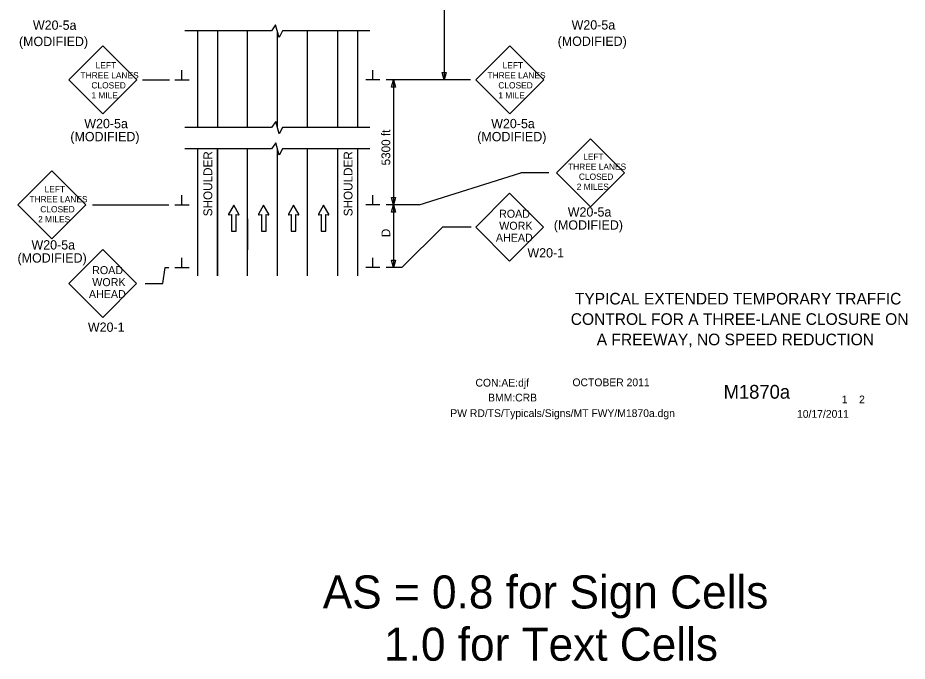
# Model space of a CAD drawing. Extents: x 16724 to 18475, y 7025 to 8210.
# Drawn here: x 16725 to 17436, y 7025 to 7539 of the extents above; entities that cross this region are included whole.
import ezdxf

# ---------------------------------------------------------------- set-up
doc = ezdxf.new("R2010")
doc.units = 0
for name, color, linetype in [('BORDER', 7, 'Continuous'), ('BORDER_SIGNAL_WO', 7, 'Continuous'), ('Level 3', 7, 'Continuous'), ('MT_SCRATCH_LEVEL_E', 7, 'Continuous'), ('PAVT_EDGE_EX', 7, 'Continuous'), ('TRAFFIC_SIGNS_PR', 7, 'Continuous'), ('TYPICAL_TEXT_DIMEN_PR', 7, 'Continuous')]:
    doc.layers.add(name, color=color, linetype=linetype)

msp = doc.modelspace()

# ---------------------------------------------------------------- linework, layer by layer
at = {"layer": 'Level 3'}
msp.add_line((16840.68, 7326.73), (16842.33, 7339.56), dxfattribs=at)
at = {"layer": 'MT_SCRATCH_LEVEL_E'}
for p, q in [((16897.35, 7389.48), (16893.24, 7382.24)), ((16901.49, 7382.24), (16897.35, 7389.48)), ((16921.25, 7389.48), (16917.14, 7382.24)), ((16925.4, 7382.24), (16921.25, 7389.48)), ((16945.16, 7389.48), (16941.05, 7382.24)), ((16949.3, 7382.24), (16945.16, 7389.48)), ((16969.21, 7389.48), (16965.1, 7382.24)), ((16973.36, 7382.24), (16969.21, 7389.48)), ((16893.72, 7381.55), (16895.5, 7381.87)), ((16895.5, 7381.87), (16895.5, 7368.61)), ((16899.24, 7368.61), (16899.24, 7381.87)), ((16899.24, 7381.87), (16901.02, 7381.55)), ((16917.62, 7381.55), (16919.4, 7381.87)), ((16919.4, 7381.87), (16919.4, 7368.61)), ((16923.14, 7368.61), (16923.14, 7381.87)), ((16923.14, 7381.87), (16924.92, 7381.55)), ((16941.53, 7381.55), (16943.3, 7381.87)), ((16943.3, 7381.87), (16943.3, 7368.61)), ((16947.05, 7368.61), (16947.05, 7381.87)), ((16947.05, 7381.87), (16948.82, 7381.55)), ((16965.58, 7381.55), (16967.36, 7381.87)), ((16967.36, 7381.87), (16967.36, 7368.61)), ((16971.1, 7368.61), (16971.1, 7381.87)), ((16971.1, 7381.87), (16972.88, 7381.55)), ((16895.5, 7368.61), (16899.24, 7368.61)), ((16919.4, 7368.61), (16923.14, 7368.61)), ((16943.3, 7368.61), (16947.05, 7368.61)), ((16967.36, 7368.61), (16971.1, 7368.61))]:
    msp.add_line(p, q, dxfattribs=at)
for centre, start, end in [((16893.64, 7382.01), 150.42484, 279.96381), ((16901.09, 7382.01), 260.03619, 29.77312), ((16917.55, 7382.01), 150.42484, 279.96381), ((16924.99, 7382.01), 260.03619, 29.77312), ((16941.45, 7382.01), 150.42484, 279.96381), ((16948.89, 7382.01), 260.03619, 29.77312), ((16965.51, 7382.01), 150.42484, 279.96381), ((16972.95, 7382.01), 260.03619, 29.77312)]:
    msp.add_arc(centre, 0.463, start, end, dxfattribs=at)
at = {"layer": 'PAVT_EDGE_EX'}
for p, q in [((16868.3, 7528.66), (16868.3, 7451.52)), ((16884.3, 7528.66), (16884.3, 7451.52)), ((16908.3, 7451.52), (16908.3, 7528.66)), ((16932.3, 7451.52), (16932.3, 7528.67)), ((16956.3, 7451.52), (16956.3, 7528.67)), ((16980.3, 7528.67), (16980.3, 7451.52)), ((16996.3, 7528.67), (16996.3, 7451.52)), ((16868.3, 7434.38), (16868.3, 7332.84)), ((16884.3, 7332.84), (16884.3, 7434.38)), ((16884.3, 7434.38), (16884.3, 7332.84)), ((16908.3, 7332.84), (16908.3, 7434.38)), ((16932.3, 7332.84), (16932.3, 7434.11)), ((16956.3, 7332.84), (16956.3, 7434.38)), ((16980.3, 7434.38), (16980.3, 7332.84)), ((16996.3, 7434.38), (16996.3, 7332.84))]:
    msp.add_line(p, q, dxfattribs=at)
for points in [[(16908.3, 7451.52), (16908.3, 7476.52)], [(16932.3, 7451.52), (16932.3, 7476.52)], [(16956.3, 7451.52), (16956.3, 7476.52)], [(16908.3, 7378.56), (16908.3, 7353.56)], [(16908.3, 7378.56), (16908.3, 7353.56)], [(16932.3, 7353.56), (16932.3, 7378.56)], [(16956.3, 7353.56), (16956.3, 7378.56)]]:
    msp.add_lwpolyline(points, dxfattribs=at)
at = {"layer": 'TRAFFIC_SIGNS_PR'}
for p, q in [((16792.64, 7516.75), (16765.45, 7489.56)), ((16819.83, 7489.56), (16792.64, 7516.75)), ((17118.16, 7516.75), (17090.97, 7489.56)), ((17145.35, 7489.56), (17118.16, 7516.75)), ((16765.45, 7489.56), (16792.64, 7462.38)), ((16792.64, 7462.38), (16819.83, 7489.56)), ((17090.97, 7489.56), (17118.16, 7462.38)), ((17118.16, 7462.38), (17145.35, 7489.56)), ((17182.61, 7442.43), (17155.43, 7415.25)), ((17209.8, 7415.25), (17182.61, 7442.43)), ((16751.74, 7416.75), (16724.56, 7389.56)), ((16778.93, 7389.56), (16751.74, 7416.75)), ((17155.43, 7415.25), (17182.61, 7388.06)), ((17182.61, 7388.06), (17209.8, 7415.25)), ((17118.04, 7398.93), (17090.89, 7371.78)), ((17145.19, 7371.78), (17118.04, 7398.93)), ((16724.56, 7389.56), (16751.74, 7362.38)), ((16751.74, 7362.38), (16778.93, 7389.56)), ((17090.89, 7371.78), (17118.04, 7344.63)), ((17118.04, 7344.63), (17145.19, 7371.78)), ((16792.48, 7353.85), (16765.33, 7326.7)), ((16819.64, 7326.7), (16792.48, 7353.85)), ((16765.33, 7326.7), (16792.48, 7299.54)), ((16792.48, 7299.54), (16819.64, 7326.7))]:
    msp.add_line(p, q, dxfattribs=at)
at = {"layer": 'TYPICAL_TEXT_DIMEN_PR'}
for p, q in [((17065.73, 7768.35), (17065.73, 7489.56)), ((16927.55, 7528.66), (16858.21, 7528.66)), ((16930.81, 7533.46), (16927.55, 7528.66)), ((16933.55, 7523.52), (16930.81, 7533.46)), ((16936.29, 7528.66), (16933.55, 7523.52)), ((17006.21, 7528.66), (16936.29, 7528.66)), ((16855.92, 7489.56), (16855.92, 7497.35)), ((17008.67, 7489.56), (17008.67, 7497.35)), ((17065.73, 7489.56), (17064.16, 7495.43)), ((17064.16, 7495.43), (17065.73, 7495.43)), ((17065.73, 7495.43), (17067.3, 7495.43)), ((17067.3, 7495.43), (17065.73, 7489.56)), ((16824.3, 7489.56), (16846.01, 7489.56)), ((16850.3, 7489.56), (16861.55, 7489.56)), ((17014.3, 7489.56), (17003.05, 7489.56)), ((17086.8, 7489.56), (17019.3, 7489.56)), ((17023.51, 7483.7), (17025.08, 7489.56)), ((17025.08, 7489.56), (17025.08, 7389.56)), ((17025.08, 7489.56), (17026.65, 7483.7)), ((17025.08, 7483.7), (17023.51, 7483.7)), ((17026.65, 7483.7), (17025.08, 7483.7)), ((16927.64, 7451.5), (16858.3, 7451.5)), ((16930.9, 7456.3), (16927.64, 7451.5)), ((16933.64, 7446.36), (16930.9, 7456.3)), ((16936.38, 7451.5), (16933.64, 7446.36)), ((17006.3, 7451.5), (16936.38, 7451.5)), ((16930.9, 7439.22), (16927.64, 7434.42)), ((16933.64, 7429.28), (16930.9, 7439.22)), ((16927.64, 7434.42), (16858.3, 7434.42)), ((16936.38, 7434.42), (16933.64, 7429.28)), ((17006.3, 7434.42), (16936.38, 7434.42)), ((17045.59, 7389.56), (17127.11, 7415.25)), ((17149.5, 7415.25), (17127.11, 7415.25)), ((16855.92, 7389.56), (16855.92, 7397.35)), ((17008.67, 7389.56), (17008.67, 7397.35)), ((17025.08, 7389.56), (17023.51, 7395.43)), ((17023.51, 7395.43), (17025.08, 7395.43)), ((17025.08, 7395.43), (17026.65, 7395.43)), ((17026.65, 7395.43), (17025.08, 7389.56)), ((16784.29, 7389.56), (16845.3, 7389.56)), ((16850.3, 7389.56), (16861.55, 7389.56)), ((17014.3, 7389.56), (17003.05, 7389.56)), ((17045.59, 7389.56), (17019.3, 7389.56)), ((17023.51, 7383.7), (17025.08, 7389.56)), ((17025.08, 7389.56), (17025.08, 7339.56)), ((17025.08, 7389.56), (17026.65, 7383.7)), ((17025.08, 7383.7), (17023.51, 7383.7)), ((17026.65, 7383.7), (17025.08, 7383.7)), ((17064.22, 7371.82), (17031.69, 7339.56)), ((17087.3, 7371.82), (17064.22, 7371.82)), ((16855.92, 7339.56), (16855.92, 7347.35)), ((17008.67, 7339.56), (17008.67, 7347.35)), ((17025.08, 7339.56), (17023.51, 7345.43)), ((17023.51, 7345.43), (17025.08, 7345.43)), ((17025.08, 7345.43), (17026.65, 7345.43)), ((17026.65, 7345.43), (17025.08, 7339.56)), ((16842.33, 7339.56), (16845.3, 7339.56)), ((16850.3, 7339.56), (16861.55, 7339.56)), ((17014.3, 7339.56), (17003.05, 7339.56)), ((17031.69, 7339.56), (17019.3, 7339.56)), ((16826.4, 7326.73), (16840.68, 7326.73))]:
    msp.add_line(p, q, dxfattribs=at)

# ---------------------------------------------------------------- texts
at = {"layer": 'BORDER'}
for s, p in [('TYPICAL EXTENDED TEMPORARY TRAFFIC', (17170.19, 7309.95)), ('CONTROL FOR A THREE-LANE CLOSURE ON', (17166.91, 7293.65)), ('A FREEWAY, NO SPEED REDUCTION', (17187.69, 7277.35))]:
    msp.add_text(s, height=9.3, dxfattribs=at).set_placement(p)
at = {"layer": 'BORDER_SIGNAL_WO'}
for s, height, p in [('CON:AE:djf  ', 6.2, (17090.69, 7244.31)), ('    OCTOBER 2011', 6.2, (17159.08, 7244.59)), ('    M1870a   ', 11, (17272.86, 7234.63)), ('BMM:CRB', 6.2, (17100.81, 7232.42)), (' 1    2 ', 6.2, (17381.45, 7230.95)), ('PW RD/TS/Typicals/Signs/MT FWY/M1870a.dgn      ', 6.2, (17070.55, 7219.96)), ('10/17/2011', 6.2, (17347.93, 7219.38)), ('AS = 0.8 for Sign Cells', 26.4241, (16968.52, 7066.89)), ('     1.0 for Text Cells', 26.4241, (16968.52, 7025.11))]:
    msp.add_text(s, height=height, dxfattribs=at).set_placement(p)
at = {"layer": 'TRAFFIC_SIGNS_PR'}
for s, height, p in [('W20-5a', 7.44, (16736.67, 7529.6)), ('W20-5a', 7.44, (17167.61, 7529.8)), ('(MODIFIED)', 7.44, (16725.53, 7516.56)), ('(MODIFIED)', 7.44, (17156.46, 7516.76)), ('LEFT', 5.006, (16786.88, 7498.71)), ('LEFT', 5.006, (17112.4, 7498.71)), ('THREE LANES', 5.0062, (16774.76, 7490.71)), ('THREE LANES', 5.0062, (17100.28, 7490.71)), ('CLOSED', 5.006, (16783.46, 7482.7)), ('CLOSED', 5.006, (17108.98, 7482.7)), ('1 MILE', 5.006, (16783.46, 7474.69)), ('1 MILE', 5.006, (17108.98, 7474.69)), ('W20-5a', 7.449, (16777.76, 7450.92)), ('W20-5a', 7.449, (17103.28, 7450.92)), ('(MODIFIED)', 7.449, (16766.6, 7440.47)), ('(MODIFIED)', 7.449, (17092.12, 7440.47)), ('LEFT', 5.006, (17176.86, 7425.64)), ('THREE LANES', 5.0062, (17164.74, 7417.64)), ('CLOSED', 5.006, (17173.44, 7409.63)), ('LEFT', 5.006, (16745.99, 7399.62)), ('2 MILES', 5.006, (17171.69, 7401.62)), ('THREE LANES', 5.0062, (16733.87, 7391.62)), ('CLOSED', 5.006, (16742.57, 7383.61)), ('ROAD', 6.4, (17109.58, 7379.32)), ('W20-5a', 7.449, (17164.52, 7380.24)), ('2 MILES', 5.006, (16740.82, 7375.6)), ('WORK', 6.4, (17109.69, 7369.72)), ('(MODIFIED)', 7.449, (17153.37, 7369.78)), ('AHEAD', 6.4, (17107, 7360.12)), ('W20-5a', 7.449, (16735.52, 7353.91)), ('(MODIFIED)', 7.449, (16724.37, 7343.46)), ('W20-1', 7.44, (17132.27, 7347.53)), ('ROAD', 6.4, (16784.02, 7334.23)), ('WORK', 6.4, (16784.13, 7324.63)), ('AHEAD', 6.4, (16781.44, 7315.03)), ('W20-1', 7.44, (16780.65, 7288.1))]:
    msp.add_text(s, height=height, dxfattribs=at).set_placement(p)
at = {"layer": 'TYPICAL_TEXT_DIMEN_PR'}
for s, p in [('5300 ft', (17022.52, 7421.17)), ('SHOULDER', (16880.1, 7380.51)), ('SHOULDER', (16992.3, 7380.51)), ('D', (17022.52, 7363.78))]:
    msp.add_text(s, height=7, rotation=90, dxfattribs=at).set_placement(p)

doc.saveas('drawing.dxf')
